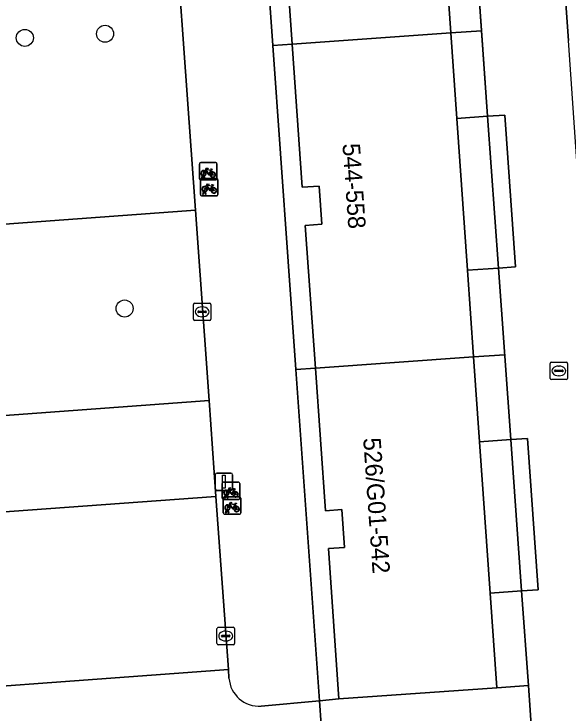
# Model space of a CAD drawing. Extents: x 161248 to 161848, y 384871 to 385383.
# Drawn here: x 161748.82 to 161780.53, y 385133.84 to 385173.89 of the extents above; entities that cross this region are included whole.
import ezdxf

# ---------------------------------------------------------------- set-up
doc = ezdxf.new("R2010")
doc.units = 0
for name, color, linetype in [('IMGEO_Boom', 7, 'Continuous'), ('IMGEO_Fietsenrek', 7, 'Continuous'), ('IMGEO_Groenvoorziening', 7, 'Continuous'), ('IMGEO_Kolk', 7, 'Continuous'), ('IMGEO_Lichtmast', 7, 'Continuous'), ('IMGEO_Pand', 7, 'Continuous'), ('IMGEO_Pand_nummerreeks', 7, 'Continuous'), ('IMGEO_Pand_overbouw', 7, 'Continuous'), ('IMGEO_Parkeervlak_open', 7, 'Continuous'), ('IMGEO_Rijbaan_lokaal_open', 7, 'Continuous'), ('IMGEO_Rioolput', 7, 'Continuous'), ('IMGEO_Voetpad_open', 7, 'Continuous')]:
    doc.layers.add(name, color=color, linetype=linetype)

msp = doc.modelspace()

# ---------------------------------------------------------------- linework, layer by layer
at = {"layer": 'IMGEO_Boom'}
for centre in [(161749.44, 385172.52), (161754.033, 385172.754), (161755.153, 385157.013)]:
    msp.add_circle(centre, 0.489, dxfattribs=at)
at = {"layer": 'IMGEO_Fietsenrek'}
for p, q in [((161759.432, 385164.453), (161759.432, 385165.294)), ((161759.432, 385165.294), (161759.432, 385164.453)), ((161759.507, 385165.378), (161760.348, 385165.378)), ((161760.348, 385165.378), (161759.507, 385165.378)), ((161760.432, 385165.303), (161760.432, 385164.462)), ((161760.432, 385164.462), (161760.432, 385165.303)), ((161760.119, 385164.927), (161760.155, 385164.832)), ((161759.559, 385164.462), (161759.598, 385164.622)), ((161759.628, 385164.61), (161759.593, 385164.462)), ((161759.67, 385164.634), (161759.669, 385164.638)), ((161759.711, 385164.462), (161759.677, 385164.604)), ((161759.701, 385164.645), (161759.702, 385164.638)), ((161759.709, 385164.608), (161759.744, 385164.462)), ((161759.497, 385163.545), (161759.497, 385164.386)), ((161759.497, 385164.386), (161759.497, 385163.545)), ((161760.357, 385164.378), (161759.516, 385164.378)), ((161759.516, 385164.378), (161760.357, 385164.378)), ((161759.593, 385164.462), (161759.559, 385164.462)), ((161759.572, 385164.47), (161760.413, 385164.47)), ((161760.413, 385164.47), (161759.572, 385164.47)), ((161759.744, 385164.462), (161759.711, 385164.462)), ((161760.497, 385164.395), (161760.497, 385163.554)), ((161760.497, 385163.554), (161760.497, 385164.395)), ((161759.624, 385163.554), (161759.663, 385163.714)), ((161759.693, 385163.702), (161759.658, 385163.554)), ((161759.735, 385163.726), (161759.734, 385163.73)), ((161759.776, 385163.554), (161759.742, 385163.696)), ((161759.766, 385163.737), (161759.767, 385163.73)), ((161759.774, 385163.7), (161759.809, 385163.554)), ((161760.184, 385164.019), (161760.22, 385163.924)), ((161760.422, 385163.47), (161759.581, 385163.47)), ((161759.581, 385163.47), (161760.422, 385163.47)), ((161759.658, 385163.554), (161759.624, 385163.554)), ((161759.809, 385163.554), (161759.776, 385163.554)), ((161760.741, 385146.14), (161760.741, 385146.981)), ((161760.741, 385146.981), (161760.741, 385146.14)), ((161760.816, 385147.065), (161761.657, 385147.065)), ((161761.657, 385147.065), (161760.816, 385147.065)), ((161761.741, 385146.99), (161761.741, 385146.149)), ((161761.741, 385146.149), (161761.741, 385146.99)), ((161761.428, 385146.614), (161761.464, 385146.519)), ((161760.801, 385145.302), (161760.801, 385146.143)), ((161760.801, 385146.143), (161760.801, 385145.302)), ((161761.666, 385146.065), (161760.825, 385146.065)), ((161760.825, 385146.065), (161761.666, 385146.065)), ((161760.868, 385146.149), (161760.907, 385146.309)), ((161760.902, 385146.149), (161760.868, 385146.149)), ((161760.876, 385146.227), (161761.717, 385146.227)), ((161761.717, 385146.227), (161760.876, 385146.227)), ((161760.937, 385146.297), (161760.902, 385146.149)), ((161760.979, 385146.321), (161760.978, 385146.325)), ((161761.02, 385146.149), (161760.986, 385146.291)), ((161761.01, 385146.332), (161761.011, 385146.325)), ((161761.018, 385146.295), (161761.053, 385146.149)), ((161761.053, 385146.149), (161761.02, 385146.149)), ((161761.801, 385146.152), (161761.801, 385145.311)), ((161761.801, 385145.311), (161761.801, 385146.152)), ((161761.488, 385145.776), (161761.524, 385145.681)), ((161760.928, 385145.311), (161760.967, 385145.471)), ((161760.962, 385145.311), (161760.928, 385145.311)), ((161760.997, 385145.459), (161760.962, 385145.311)), ((161761.039, 385145.483), (161761.038, 385145.487)), ((161761.08, 385145.311), (161761.046, 385145.453)), ((161761.07, 385145.494), (161761.071, 385145.487)), ((161761.078, 385145.457), (161761.113, 385145.311)), ((161761.113, 385145.311), (161761.08, 385145.311)), ((161761.726, 385145.227), (161760.885, 385145.227)), ((161760.885, 385145.227), (161761.726, 385145.227))]:
    msp.add_line(p, q, dxfattribs=at)
for points in [[(161759.745, 385164.904), (161759.84, 385165.068), (161759.926, 385165.054), (161759.928, 385165.045), (161759.872, 385165.034), (161759.845, 385164.989), (161760.101, 385164.948)], [(161760.041, 385164.66), (161759.991, 385164.66), (161759.8, 385164.911), (161759.781, 385164.879)], [(161760.088, 385164.923), (161759.831, 385164.964), (161759.814, 385164.935), (161759.981, 385164.715), (161760.088, 385164.923)], [(161760.136, 385164.825), (161760.106, 385164.902), (161759.997, 385164.684), (161760.04, 385164.684)], [(161760.101, 385164.948), (161760.126, 385164.997), (161760.12, 385165.001), (161760.097, 385165.005), (161760.085, 385165.012), (161760.084, 385165.015), (161760.086, 385165.02), (161760.181, 385165.005), (161760.183, 385164.995), (161760.173, 385164.982), (161760.161, 385164.976), (161760.147, 385164.982), (161760.119, 385164.927)], [(161759.766, 385164.852), (161759.714, 385164.762), (161759.674, 385164.737), (161759.675, 385164.784), (161759.73, 385164.878)], [(161760.07, 385164.684), (161760.19, 385164.683), (161760.146, 385164.797)], [(161760.166, 385164.804), (161760.221, 385164.659), (161760.071, 385164.659)], [(161759.81, 385163.996), (161759.905, 385164.16), (161759.991, 385164.146), (161759.993, 385164.137), (161759.937, 385164.126), (161759.91, 385164.081), (161760.166, 385164.04)], [(161760.166, 385164.04), (161760.191, 385164.089), (161760.185, 385164.093), (161760.162, 385164.097), (161760.15, 385164.104), (161760.149, 385164.107), (161760.151, 385164.112), (161760.246, 385164.097), (161760.248, 385164.087), (161760.238, 385164.074), (161760.226, 385164.068), (161760.212, 385164.074), (161760.184, 385164.019)], [(161759.831, 385163.944), (161759.779, 385163.854), (161759.739, 385163.829), (161759.74, 385163.876), (161759.795, 385163.97)], [(161760.106, 385163.752), (161760.056, 385163.752), (161759.865, 385164.003), (161759.846, 385163.971)], [(161760.153, 385164.015), (161759.896, 385164.056), (161759.879, 385164.027), (161760.046, 385163.807), (161760.153, 385164.015)], [(161760.201, 385163.917), (161760.171, 385163.994), (161760.062, 385163.776), (161760.105, 385163.776)], [(161760.135, 385163.776), (161760.255, 385163.775), (161760.211, 385163.889)], [(161760.231, 385163.896), (161760.286, 385163.751), (161760.136, 385163.751)], [(161761.075, 385146.539), (161761.023, 385146.449), (161760.983, 385146.424), (161760.984, 385146.471), (161761.039, 385146.565)], [(161761.054, 385146.591), (161761.149, 385146.755), (161761.235, 385146.741), (161761.237, 385146.732), (161761.181, 385146.721), (161761.154, 385146.676), (161761.41, 385146.635)], [(161761.35, 385146.347), (161761.3, 385146.347), (161761.109, 385146.598), (161761.09, 385146.566)], [(161761.397, 385146.61), (161761.14, 385146.651), (161761.123, 385146.622), (161761.29, 385146.402), (161761.397, 385146.61)], [(161761.445, 385146.512), (161761.415, 385146.589), (161761.306, 385146.371), (161761.349, 385146.371)], [(161761.379, 385146.371), (161761.499, 385146.37), (161761.455, 385146.484)], [(161761.475, 385146.491), (161761.53, 385146.346), (161761.38, 385146.346)], [(161761.41, 385146.635), (161761.435, 385146.684), (161761.429, 385146.688), (161761.406, 385146.692), (161761.394, 385146.699), (161761.393, 385146.702), (161761.395, 385146.707), (161761.49, 385146.692), (161761.492, 385146.682), (161761.482, 385146.669), (161761.47, 385146.663), (161761.456, 385146.669), (161761.428, 385146.614)], [(161761.135, 385145.701), (161761.083, 385145.611), (161761.043, 385145.586), (161761.044, 385145.633), (161761.099, 385145.727)], [(161761.114, 385145.753), (161761.209, 385145.917), (161761.295, 385145.903), (161761.297, 385145.894), (161761.241, 385145.883), (161761.214, 385145.838), (161761.47, 385145.797)], [(161761.41, 385145.509), (161761.36, 385145.509), (161761.169, 385145.76), (161761.15, 385145.728)], [(161761.457, 385145.772), (161761.2, 385145.813), (161761.183, 385145.784), (161761.35, 385145.564), (161761.457, 385145.772)], [(161761.505, 385145.674), (161761.475, 385145.751), (161761.366, 385145.533), (161761.409, 385145.533)], [(161761.47, 385145.797), (161761.495, 385145.846), (161761.489, 385145.85), (161761.466, 385145.854), (161761.454, 385145.861), (161761.453, 385145.864), (161761.455, 385145.869), (161761.55, 385145.854), (161761.552, 385145.844), (161761.542, 385145.831), (161761.53, 385145.825), (161761.516, 385145.831), (161761.488, 385145.776)], [(161761.439, 385145.533), (161761.559, 385145.532), (161761.515, 385145.646)], [(161761.535, 385145.653), (161761.59, 385145.508), (161761.44, 385145.508)]]:
    msp.add_lwpolyline(points, dxfattribs=at)
for centre, radius, start, end in [((161759.51, 385165.3), 0.0779, 92.4484, 184.2845), ((161759.51, 385165.3), 0.0779, 92.4484, 184.2845), ((161760.354, 385165.3), 0.0779, 2.4484, 94.2845), ((161760.354, 385165.3), 0.0779, 2.4484, 94.2845), ((161759.672, 385164.763), 0.159, 62.6766, 242.1369), ((161759.672, 385164.763), 0.129, 63.3192, 238.903), ((161759.652, 385164.634), 0.0499, 12.8025, 158.6934), ((161759.672, 385164.763), 0.159, 253.9967, 271.7867), ((161759.652, 385164.634), 0.0174, 12.8025, 163.4502), ((161759.672, 385164.763), 0.129, 253.415, 269.0204), ((161759.672, 385164.763), 0.129, 283.6043, 43.4302), ((161759.672, 385164.763), 0.159, 283.5766, 46.6042), ((161760.199, 385164.679), 0.159, 113.3408, 178.3217), ((161760.199, 385164.679), 0.159, 187.0065, 105.7708), ((161760.199, 385164.679), 0.129, 113.923, 177.9556), ((161760.199, 385164.679), 0.129, 188.6715, 104.5883), ((161759.51, 385164.456), 0.0779, 182.4484, 274.2845), ((161759.51, 385164.456), 0.0779, 182.4484, 274.2845), ((161759.575, 385164.392), 0.0779, 92.4484, 184.2845), ((161759.575, 385164.392), 0.0779, 92.4484, 184.2845), ((161760.354, 385164.456), 0.0779, 272.4484, 4.2845), ((161760.354, 385164.456), 0.0779, 272.4484, 4.2845), ((161760.419, 385164.392), 0.0779, 2.4484, 94.2845), ((161760.419, 385164.392), 0.0779, 2.4484, 94.2845), ((161759.737, 385163.855), 0.159, 62.6766, 242.1369), ((161759.737, 385163.855), 0.129, 63.3192, 238.903), ((161759.717, 385163.726), 0.0499, 12.8025, 158.6934), ((161759.737, 385163.855), 0.159, 253.9967, 271.7867), ((161759.717, 385163.726), 0.0174, 12.8025, 163.4502), ((161759.737, 385163.855), 0.129, 253.415, 269.0204), ((161759.737, 385163.855), 0.129, 283.6043, 43.4302), ((161759.737, 385163.855), 0.159, 283.5766, 46.6042), ((161760.264, 385163.771), 0.159, 113.3408, 178.3217), ((161760.264, 385163.771), 0.159, 187.0065, 105.7708), ((161760.264, 385163.771), 0.129, 113.923, 177.9556), ((161760.264, 385163.771), 0.129, 188.6715, 104.5883), ((161759.575, 385163.548), 0.0779, 182.4484, 274.2845), ((161759.575, 385163.548), 0.0779, 182.4484, 274.2845), ((161760.419, 385163.548), 0.0779, 272.4484, 4.2845), ((161760.419, 385163.548), 0.0779, 272.4484, 4.2845), ((161760.819, 385146.987), 0.0779, 92.4484, 184.2845), ((161760.819, 385146.987), 0.0779, 92.4484, 184.2845), ((161761.663, 385146.987), 0.0779, 2.4484, 94.2845), ((161761.663, 385146.987), 0.0779, 2.4484, 94.2845), ((161760.981, 385146.45), 0.159, 62.6766, 242.1369), ((161760.981, 385146.45), 0.129, 63.3192, 238.903), ((161760.981, 385146.45), 0.129, 283.6043, 43.4302), ((161760.981, 385146.45), 0.159, 283.5766, 46.6042), ((161761.508, 385146.366), 0.159, 113.3408, 178.3217), ((161761.508, 385146.366), 0.159, 187.0065, 105.7708), ((161761.508, 385146.366), 0.129, 113.923, 177.9556), ((161761.508, 385146.366), 0.129, 188.6715, 104.5883), ((161760.819, 385146.143), 0.0779, 182.4484, 274.2845), ((161760.819, 385146.143), 0.0779, 182.4484, 274.2845), ((161760.879, 385146.149), 0.0779, 92.4484, 184.2845), ((161760.879, 385146.149), 0.0779, 92.4484, 184.2845), ((161760.961, 385146.321), 0.0499, 12.8025, 158.6934), ((161760.981, 385146.45), 0.159, 253.9967, 271.7867), ((161760.961, 385146.321), 0.0174, 12.8025, 163.4502), ((161760.981, 385146.45), 0.129, 253.415, 269.0204), ((161761.663, 385146.143), 0.0779, 272.4484, 4.2845), ((161761.663, 385146.143), 0.0779, 272.4484, 4.2845), ((161761.723, 385146.149), 0.0779, 2.4484, 94.2845), ((161761.723, 385146.149), 0.0779, 2.4484, 94.2845), ((161761.041, 385145.612), 0.159, 62.6766, 242.1369), ((161761.041, 385145.612), 0.129, 63.3192, 238.903), ((161761.041, 385145.612), 0.129, 283.6043, 43.4302), ((161761.041, 385145.612), 0.159, 283.5766, 46.6042), ((161761.568, 385145.528), 0.159, 113.3408, 178.3217), ((161761.568, 385145.528), 0.159, 187.0065, 105.7708), ((161760.879, 385145.305), 0.0779, 182.4484, 274.2845), ((161760.879, 385145.305), 0.0779, 182.4484, 274.2845), ((161761.021, 385145.483), 0.0499, 12.8025, 158.6934), ((161761.041, 385145.612), 0.159, 253.9967, 271.7867), ((161761.021, 385145.483), 0.0174, 12.8025, 163.4502), ((161761.041, 385145.612), 0.129, 253.415, 269.0204), ((161761.568, 385145.528), 0.129, 113.923, 177.9556), ((161761.568, 385145.528), 0.129, 188.6715, 104.5883), ((161761.723, 385145.305), 0.0779, 272.4484, 4.2845), ((161761.723, 385145.305), 0.0779, 272.4484, 4.2845)]:
    msp.add_arc(centre, radius, start, end, dxfattribs=at)
at = {"layer": 'IMGEO_Groenvoorziening'}
msp.add_lwpolyline([(161779.295, 385189.961), (161780.557, 385172.377)], dxfattribs=at)
at = {"layer": 'IMGEO_Kolk'}
for p, q in [((161759.166, 385157.326), (161760.018, 385157.326)), ((161759.091, 385156.4), (161759.091, 385157.252)), ((161759.579, 385157.106), (161759.604, 385157.106)), ((161760.092, 385157.252), (161760.092, 385156.4)), ((161759.35, 385156.82), (161759.35, 385156.832)), ((161759.788, 385156.783), (161759.39, 385156.783)), ((161759.393, 385156.869), (161759.791, 385156.869)), ((161759.602, 385156.546), (161759.577, 385156.546)), ((161759.834, 385156.832), (161759.834, 385156.82)), ((161760.018, 385156.326), (161759.166, 385156.326)), ((161760.441, 385137.822), (161760.441, 385138.674)), ((161760.516, 385138.748), (161761.368, 385138.748)), ((161760.929, 385138.528), (161760.954, 385138.528)), ((161761.442, 385138.674), (161761.442, 385137.822)), ((161760.7, 385138.242), (161760.7, 385138.254)), ((161761.138, 385138.205), (161760.74, 385138.205)), ((161760.743, 385138.291), (161761.141, 385138.291)), ((161761.184, 385138.254), (161761.184, 385138.242)), ((161761.368, 385137.748), (161760.516, 385137.748)), ((161760.952, 385137.968), (161760.927, 385137.968))]:
    msp.add_line(p, q, dxfattribs=at)
for points in [[(161759.166, 385157.326), (161760.018, 385157.326)], [(161759.091, 385156.4), (161759.091, 385157.252)], [(161760.092, 385157.252), (161760.092, 385156.4)], [(161760.018, 385156.326), (161759.166, 385156.326)], [(161760.441, 385137.822), (161760.441, 385138.674)], [(161760.516, 385138.748), (161761.368, 385138.748)], [(161761.442, 385138.674), (161761.442, 385137.822)], [(161761.368, 385137.748), (161760.516, 385137.748)]]:
    msp.add_lwpolyline(points, dxfattribs=at)
for centre, radius, start, end in [((161759.168, 385157.25), 0.0765, 91.552, 178.448), ((161759.168, 385157.25), 0.0765, 91.552, 178.448), ((161760.016, 385157.25), 0.0765, 1.552, 88.448), ((161760.016, 385157.25), 0.0765, 1.552, 88.448), ((161759.39, 385156.829), 0.0403, 85.8775, 175.7526), ((161759.387, 385156.819), 0.0366, 178.938, 274.7102), ((161759.791, 385156.826), 0.043, 264.8664, 352.4533), ((161759.795, 385156.831), 0.0386, 1.7309, 96.639), ((161759.168, 385156.402), 0.0765, 181.552, 268.448), ((161759.168, 385156.402), 0.0765, 181.552, 268.448), ((161760.016, 385156.402), 0.0765, 271.552, 358.448), ((161760.016, 385156.402), 0.0765, 271.552, 358.448), ((161760.518, 385138.672), 0.0765, 91.552, 178.448), ((161760.518, 385138.672), 0.0765, 91.552, 178.448), ((161761.366, 385138.672), 0.0765, 1.552, 88.448), ((161761.366, 385138.672), 0.0765, 1.552, 88.448), ((161760.74, 385138.251), 0.0403, 85.8775, 175.7526), ((161760.737, 385138.241), 0.0366, 178.938, 274.7102), ((161761.141, 385138.248), 0.043, 264.8664, 352.4533), ((161761.145, 385138.253), 0.0386, 1.7309, 96.639), ((161760.518, 385137.824), 0.0765, 181.552, 268.448), ((161760.518, 385137.824), 0.0765, 181.552, 268.448), ((161761.366, 385137.824), 0.0765, 271.552, 358.448), ((161761.366, 385137.824), 0.0765, 271.552, 358.448)]:
    msp.add_arc(centre, radius, start, end, dxfattribs=at)
for centre, major_axis, ratio, start_param, end_param in [((161759.578, 385156.826), (-0.387, 0.002), 0.722429, 4.712389, 7.853982), ((161759.603, 385156.826), (-0.39, 0.002), 0.717154, 1.570796, 4.712389), ((161760.928, 385138.248), (-0.387, 0.002), 0.722429, 4.712389, 7.853982), ((161760.953, 385138.248), (-0.39, 0.002), 0.717154, 1.570796, 4.712389)]:
    msp.add_ellipse(centre, major_axis=major_axis, ratio=ratio, start_param=start_param, end_param=end_param, dxfattribs=at)
at = {"layer": 'IMGEO_Lichtmast'}
for p, q in [((161760.341, 385146.688), (161760.341, 385147.488)), ((161760.341, 385147.488), (161760.341, 385146.688)), ((161760.441, 385147.588), (161761.231, 385147.588)), ((161761.231, 385147.588), (161760.441, 385147.588)), ((161761.331, 385147.488), (161761.331, 385146.688)), ((161761.331, 385146.688), (161761.331, 385147.488)), ((161761.231, 385146.588), (161760.441, 385146.588)), ((161760.441, 385146.588), (161761.231, 385146.588))]:
    msp.add_line(p, q, dxfattribs=at)
msp.add_lwpolyline([(161760.761, 385147.463), (161760.911, 385147.463), (161760.911, 385146.713), (161760.761, 385146.713), (161760.761, 385147.463)], dxfattribs=at)
for centre, start, end in [((161760.441, 385147.488), 90, 180), ((161760.441, 385147.488), 90, 180), ((161761.231, 385147.488), 0, 90), ((161761.231, 385147.488), 360, 90), ((161760.441, 385146.688), 180, 270), ((161760.441, 385146.688), 180, 270), ((161761.231, 385146.688), 270, 0), ((161761.231, 385146.688), 270, 0)]:
    msp.add_arc(centre, 0.1, start, end, dxfattribs=at)
at = {"layer": 'IMGEO_Pand'}
for points in [[(161772.863, 385186.439), (161772.498, 385191.626), (161763.412, 385190.986), (161764.007, 385182.541), (161764.997, 385182.611), (161765.15, 385180.433), (161764.17, 385180.364), (161764.748, 385172.162), (161773.824, 385172.802), (161773.475, 385177.751)], [(161774.782, 385159.207), (161774.169, 385167.905), (161773.824, 385172.802), (161764.748, 385172.162), (161765.325, 385163.961), (161766.287, 385164.029), (161766.441, 385161.843), (161765.496, 385161.777), (161766.072, 385153.602), (161775.132, 385154.241)], [(161775.474, 385149.381), (161775.132, 385154.241), (161766.072, 385153.602), (161766.647, 385145.429), (161767.591, 385145.496), (161767.744, 385143.321), (161766.814, 385143.255), (161767.42, 385134.644), (161776.467, 385135.281), (161776.085, 385140.703)]]:
    msp.add_lwpolyline(points, close=True, dxfattribs=at)
at = {"layer": 'IMGEO_Pand_overbouw'}
for points in [[(161774.609, 385186.562), (161774.237, 385191.764), (161772.498, 385191.626), (161772.863, 385186.439), (161773.475, 385177.751), (161773.824, 385172.802), (161775.583, 385172.925), (161775.229, 385177.875)], [(161764.997, 385182.611), (161764.007, 385182.541), (161763.412, 385190.986), (161762.298, 385190.913), (161763.638, 385172.084), (161764.748, 385172.162), (161764.17, 385180.364), (161765.15, 385180.433)], [(161775.933, 385168.029), (161775.583, 385172.925), (161773.824, 385172.802), (161774.169, 385167.905), (161774.782, 385159.207), (161775.132, 385154.241), (161776.909, 385154.365), (161776.554, 385159.332)], [(161766.287, 385164.029), (161765.325, 385163.961), (161764.748, 385172.162), (161763.638, 385172.084), (161764.958, 385153.524), (161766.072, 385153.602), (161765.496, 385161.777), (161766.441, 385161.843)], [(161777.256, 385149.507), (161776.909, 385154.365), (161775.132, 385154.241), (161775.474, 385149.381), (161776.085, 385140.703), (161776.467, 385135.281), (161778.263, 385135.406), (161777.876, 385140.83)], [(161767.591, 385145.496), (161766.647, 385145.429), (161766.072, 385153.602), (161764.958, 385153.524), (161766.309, 385134.541), (161767.42, 385134.644), (161766.814, 385143.255), (161767.744, 385143.321)], [(161778.263, 385135.406), (161776.467, 385135.281), (161767.42, 385134.644), (161766.309, 385134.541), (161766.603, 385130.405), (161766.986, 385125.023), (161767.268, 385125.043), (161767.187, 385126.222), (161775.309, 385126.786), (161775.39, 385125.607), (161778.941, 385125.854), (161778.965, 385125.505), (161779.964, 385125.575), (161779.939, 385125.927), (161779.593, 385130.813), (161778.593, 385130.742), (161778.562, 385131.184)]]:
    msp.add_lwpolyline(points, close=True, dxfattribs=at)
at = {"layer": 'IMGEO_Parkeervlak_open'}
for points in [[(161759.202, 385162.654), (161742.83, 385161.454), (161743.629, 385150.549), (161759.984, 385151.748)], [(161760.378, 385146.252), (161736.996, 385144.544), (161737.736, 385134.622), (161761.09, 385136.334)]]:
    msp.add_lwpolyline(points, close=True, dxfattribs=at)
at = {"layer": 'IMGEO_Rijbaan_lokaal_open'}
for points in [[(161757.857, 385204.325), (161757.564, 385203.488), (161742.83, 385161.454), (161759.202, 385162.654), (161758.842, 385167.667), (161757.138, 385191.597)], [(161783.118, 385135.34), (161780.557, 385172.377), (161779.295, 385189.961), (161779.054, 385193.99)], [(161774.165, 385192.778), (161774.237, 385191.764), (161774.609, 385186.562), (161775.608, 385186.633), (161776.22, 385177.945), (161775.229, 385177.875), (161775.933, 385168.029), (161776.914, 385168.098), (161777.526, 385159.401), (161776.554, 385159.332), (161777.256, 385149.507), (161778.218, 385149.575), (161778.83, 385140.897), (161777.876, 385140.83), (161778.263, 385135.406), (161778.562, 385131.184), (161779.901, 385131.276)], [(161761.126, 385135.828), (161761.09, 385136.334), (161737.736, 385134.622), (161736.996, 385144.544), (161730.177, 385124.632)], [(161735.494, 385128.372), (161754.736, 385129.631), (161766.603, 385130.405), (161766.309, 385134.541)], [(161766.309, 385134.541), (161762.965, 385134.23)]]:
    msp.add_lwpolyline(points, dxfattribs=at)
for points in [[(161776.554, 385159.332), (161777.526, 385159.401), (161776.914, 385168.098), (161775.933, 385168.029)], [(161759.984, 385151.748), (161743.629, 385150.549), (161742.83, 385161.454), (161740.956, 385156.108), (161736.996, 385144.544), (161760.378, 385146.252)], [(161777.876, 385140.83), (161778.83, 385140.897), (161778.218, 385149.575), (161777.256, 385149.507)], [(161778.263, 385135.406), (161776.467, 385135.281), (161767.42, 385134.644), (161766.309, 385134.541), (161766.603, 385130.405), (161778.562, 385131.184)]]:
    msp.add_lwpolyline(points, close=True, dxfattribs=at)
msp.add_arc((161762.856, 385135.962), 1.735, 184.4282, 273.5938, dxfattribs=at)
at = {"layer": 'IMGEO_Rioolput'}
for p, q in [((161779.507, 385153.013), (161779.507, 385153.865)), ((161779.582, 385153.939), (161780.434, 385153.939)), ((161779.995, 385153.719), (161780.02, 385153.719)), ((161780.508, 385153.865), (161780.508, 385153.013)), ((161779.766, 385153.433), (161779.766, 385153.445)), ((161780.204, 385153.396), (161779.806, 385153.396)), ((161779.809, 385153.482), (161780.207, 385153.482)), ((161780.25, 385153.445), (161780.25, 385153.433)), ((161780.434, 385152.939), (161779.582, 385152.939)), ((161780.018, 385153.159), (161779.993, 385153.159))]:
    msp.add_line(p, q, dxfattribs=at)
for points in [[(161779.507, 385153.013), (161779.507, 385153.865)], [(161779.582, 385153.939), (161780.434, 385153.939)], [(161780.508, 385153.865), (161780.508, 385153.013)], [(161780.434, 385152.939), (161779.582, 385152.939)]]:
    msp.add_lwpolyline(points, dxfattribs=at)
for centre, radius, start, end in [((161779.584, 385153.863), 0.0765, 91.552, 178.448), ((161779.584, 385153.863), 0.0765, 91.552, 178.448), ((161780.432, 385153.863), 0.0765, 1.552, 88.448), ((161780.432, 385153.863), 0.0765, 1.552, 88.448), ((161779.806, 385153.442), 0.0403, 85.8775, 175.7526), ((161779.803, 385153.432), 0.0366, 178.938, 274.7102), ((161780.207, 385153.439), 0.043, 264.8664, 352.4533), ((161780.211, 385153.444), 0.0386, 1.7309, 96.639), ((161779.584, 385153.015), 0.0765, 181.552, 268.448), ((161779.584, 385153.015), 0.0765, 181.552, 268.448), ((161780.432, 385153.015), 0.0765, 271.552, 358.448), ((161780.432, 385153.015), 0.0765, 271.552, 358.448)]:
    msp.add_arc(centre, radius, start, end, dxfattribs=at)
for centre, major_axis, ratio, start_param, end_param in [((161779.994, 385153.439), (-0.387, 0.002), 0.722429, 4.712389, 7.853982), ((161780.019, 385153.439), (-0.39, 0.002), 0.717154, 1.570796, 4.712389)]:
    msp.add_ellipse(centre, major_axis=major_axis, ratio=ratio, start_param=start_param, end_param=end_param, dxfattribs=at)
at = {"layer": 'IMGEO_Voetpad_open'}
for points in [[(161764.958, 385153.524), (161763.638, 385172.084), (161762.298, 385190.913), (161763.412, 385190.986), (161772.498, 385191.626), (161774.237, 385191.764), (161774.165, 385192.778)], [(161757.138, 385191.597), (161758.842, 385167.667), (161759.202, 385162.654), (161759.984, 385151.748), (161760.378, 385146.252), (161761.09, 385136.334), (161761.126, 385135.828)], [(161762.965, 385134.23), (161766.309, 385134.541), (161764.958, 385153.524)]]:
    msp.add_lwpolyline(points, dxfattribs=at)
for points in [[(161763.638, 385172.084), (161764.748, 385172.162), (161764.17, 385180.364), (161765.15, 385180.433), (161764.997, 385182.611), (161764.007, 385182.541), (161763.412, 385190.986), (161762.298, 385190.913)], [(161775.229, 385177.875), (161773.475, 385177.751), (161773.824, 385172.802), (161774.169, 385167.905), (161775.933, 385168.029)], [(161764.958, 385153.524), (161766.072, 385153.602), (161765.496, 385161.777), (161766.441, 385161.843), (161766.287, 385164.029), (161765.325, 385163.961), (161764.748, 385172.162), (161763.638, 385172.084)], [(161775.933, 385168.029), (161774.169, 385167.905), (161774.782, 385159.207), (161776.554, 385159.332)], [(161776.554, 385159.332), (161774.782, 385159.207), (161775.132, 385154.241), (161775.474, 385149.381), (161777.256, 385149.507)], [(161767.591, 385145.496), (161766.647, 385145.429), (161766.072, 385153.602), (161764.958, 385153.524), (161766.309, 385134.541), (161767.42, 385134.644), (161766.814, 385143.255), (161767.744, 385143.321)], [(161777.256, 385149.507), (161775.474, 385149.381), (161776.085, 385140.703), (161777.876, 385140.83)], [(161777.876, 385140.83), (161776.085, 385140.703), (161776.467, 385135.281), (161778.263, 385135.406)]]:
    msp.add_lwpolyline(points, close=True, dxfattribs=at)
msp.add_arc((161762.856, 385135.962), 1.735, 184.4282, 273.5938, dxfattribs=at)

# ---------------------------------------------------------------- texts
at = {"layer": 'IMGEO_Pand_nummerreeks'}
for s, rotation, p in [('544-558', 274.0297, (161767.621, 385166.445)), ('526/G01-542', 274.0238, (161768.807, 385149.579)), ('526/G01-542', 274.0238, (161768.807, 385149.579)), ('526/G01-542', 274.0238, (161768.807, 385149.579)), ('526/G01-542', 274.0238, (161768.807, 385149.579))]:
    msp.add_text(s, height=1, rotation=rotation, dxfattribs=at).set_placement(p)

doc.saveas('drawing.dxf')
